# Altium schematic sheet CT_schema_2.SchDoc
size 307 x 173 mm
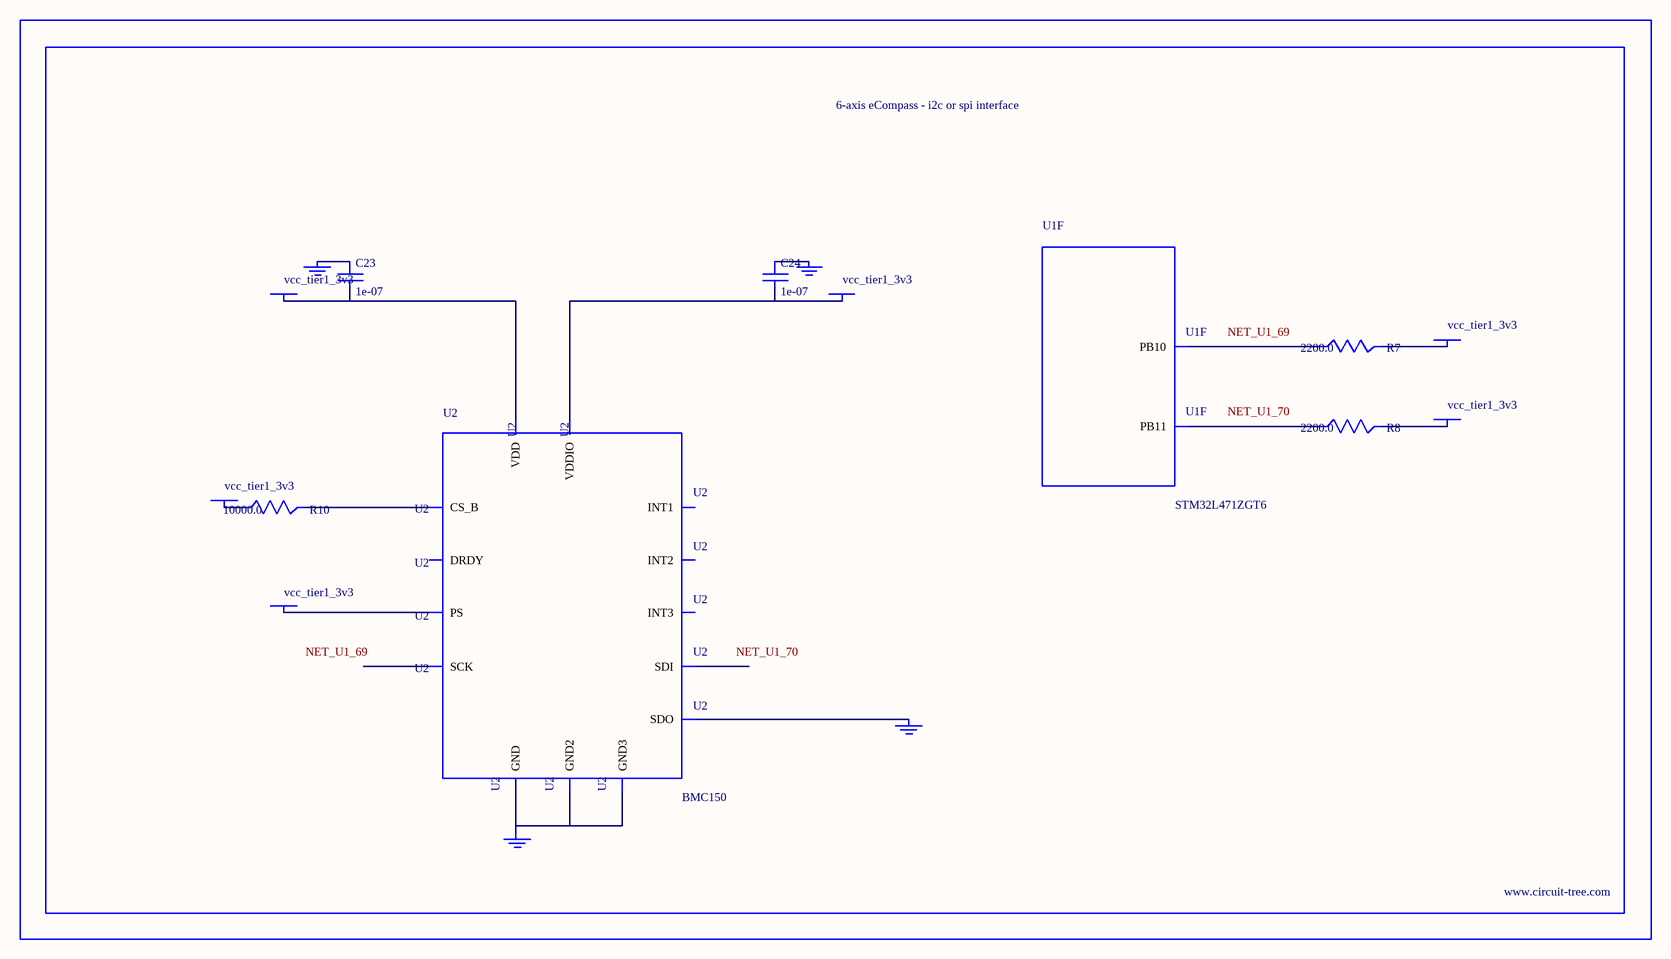
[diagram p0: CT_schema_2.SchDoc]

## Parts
BORDER1  (no value)
C23  1e-07  [C0402]
C24  1e-07  [C0402]
GND_INSTANCE_1_0  (no value)
GND_INSTANCE_1_1  (no value)
GND_INSTANCE_1_2  (no value)
GND_INSTANCE_1_3  (no value)
POWER_INSTANCE_1_0  vcc_tier1_3v3
POWER_INSTANCE_1_1  vcc_tier1_3v3
POWER_INSTANCE_1_2  vcc_tier1_3v3
POWER_INSTANCE_1_3  vcc_tier1_3v3
POWER_INSTANCE_1_4  vcc_tier1_3v3
POWER_INSTANCE_1_5  vcc_tier1_3v3
R7  2200.0  [R0603]
R8  2200.0  [R0603]
R10  10000.0  [R0603]
U1  STM32L471ZGT6  [LQFP144]  (part F of 14)
U2  BMC150  [LGA14R35P5X6_200X200X100]

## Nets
NetC23_1: C23.1 GND_INSTANCE_1_1.0(GND)
NetC23_2: C23.2 POWER_INSTANCE_1_0.0(PWR) U2.8(VDD)
NetC24_1: C24.1 GND_INSTANCE_1_2.0(GND)
NetC24_2: C24.2 POWER_INSTANCE_1_1.0(PWR) U2.10(VDDIO)
NetGND_INSTANCE_1_0_0: GND_INSTANCE_1_0.0(GND) U2.1(SDO)
NetGND_INSTANCE_1_3_0: GND_INSTANCE_1_3.0(GND) U2.6(GND) U2.7(GND2) U2.9(GND3)
NetPOWER_INSTANCE_1_2_0: POWER_INSTANCE_1_2.0(PWR) R10.1
NetPOWER_INSTANCE_1_3_0: POWER_INSTANCE_1_3.0(PWR) U2.13(PS)
NetPOWER_INSTANCE_1_4_0: POWER_INSTANCE_1_4.0(PWR) R7.2
NetPOWER_INSTANCE_1_5_0: POWER_INSTANCE_1_5.0(PWR) R8.2
NetR7_1: R7.1 U1.69(PB10)
NetR8_1: R8.1 U1.70(PB11)
NetR10_2: R10.2 U2.12(CS_B)

Not connected (* = marked no-connect by the designer): U2 2(INT1) 3(INT2) 4(DRDY) 5(INT3) 11(SCK) 14(SDI)

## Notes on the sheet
- Labels drawn without touching a wire or pin: NET_U1_69, NET_U1_70

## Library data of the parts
BORDER1 = BORDER_PAGE1
C23 C24 = C0402C104K3RACTU
GND_INSTANCE_1_0-GND_INSTANCE_1_3 = GND
POWER_INSTANCE_1_0-POWER_INSTANCE_1_5 = PWR
R7 R8 = RC0603JR-072K2L
R10 = RC0603JR-0710KL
